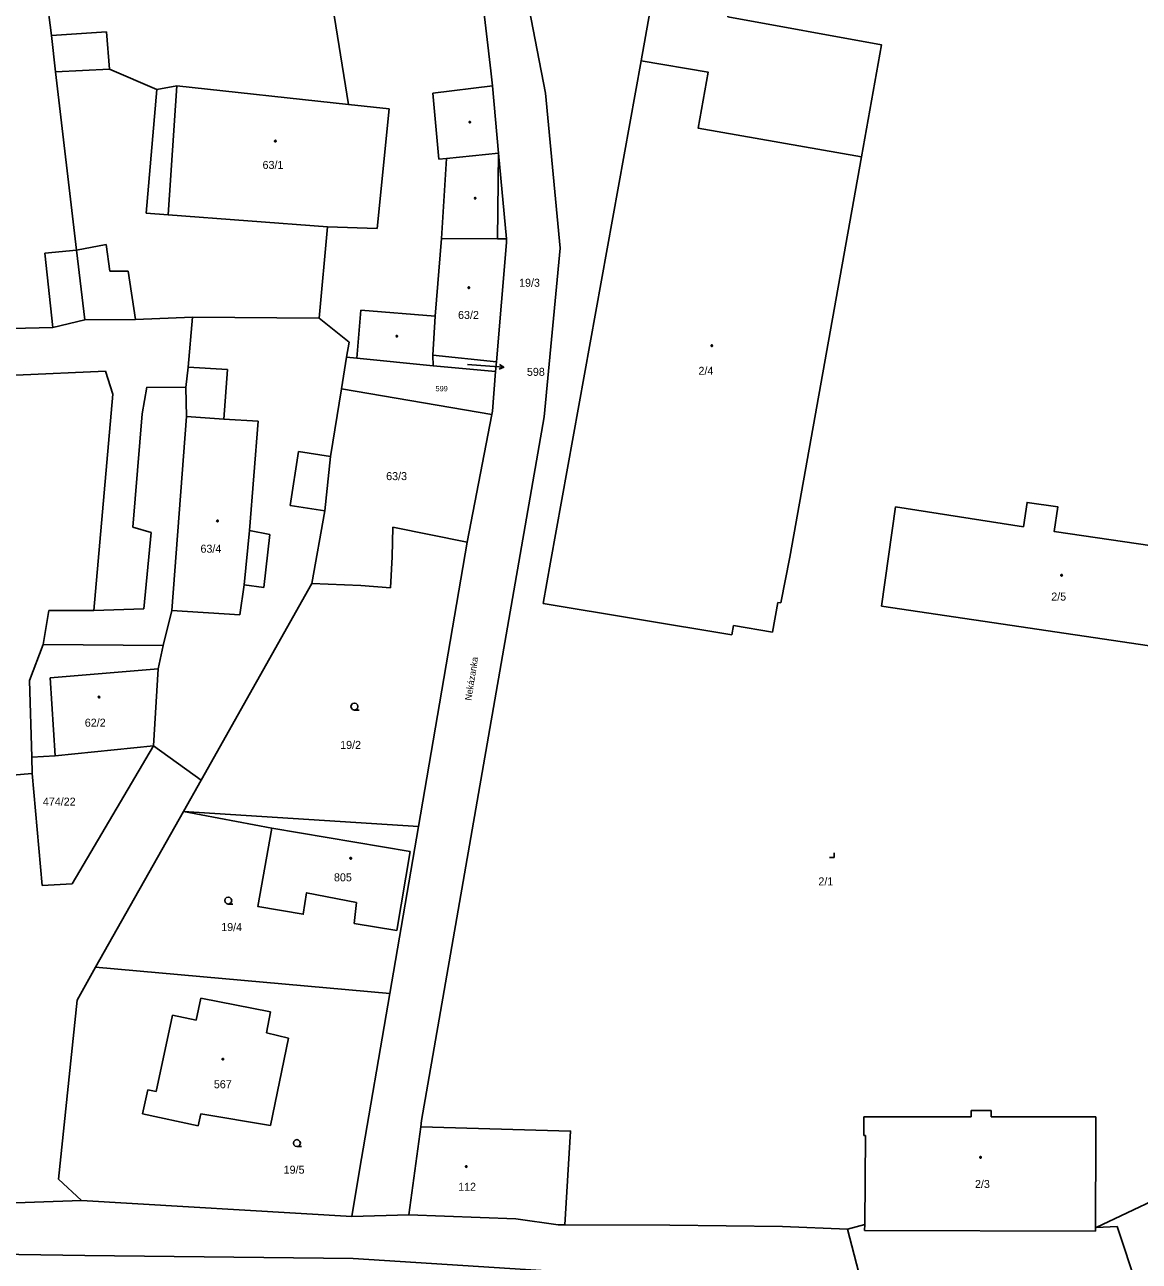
# Model space of a CAD drawing. Extents: x -757994 to -755874, y -1047691 to -1046119.
# Drawn here: x -757209.4 to -757091.1, y -1046980.7 to -1046849.4 of the extents above; entities that cross this region are included whole.
import ezdxf

# ---------------------------------------------------------------- set-up
doc = ezdxf.new("R2010")
doc.units = 0
doc.layers.add('katastrální mapa', color=7, linetype='Continuous')

msp = doc.modelspace()

# ---------------------------------------------------------------- linework, layer by layer
at = {"layer": 'katastrální mapa'}
for p, q in [((-757166.99, -1046790.73), (-757154.15, -1046856.61)), ((-757206.6, -1046850.49), (-757207.68, -1046842.04)), ((-757175.06, -1046857.82), (-757177.11, -1046845.16)), ((-757159.95, -1046854.25), (-757161.01, -1046845.29)), ((-757206.6, -1046850.49), (-757200.77, -1046850.13)), ((-757206.18, -1046854.36), (-757206.6, -1046850.49)), ((-757200.77, -1046850.13), (-757200.43, -1046854.08)), ((-757153.62, -1046906.44), (-757143.99, -1046853.18)), ((-757206.18, -1046854.36), (-757200.43, -1046854.08)), ((-757203.94, -1046873.31), (-757206.18, -1046854.36)), ((-757200.43, -1046854.08), (-757195.43, -1046856.24)), ((-757159.8, -1046855.86), (-757159.95, -1046854.25)), ((-757195.43, -1046856.24), (-757196.56, -1046869.36)), ((-757195.43, -1046856.24), (-757193.28, -1046855.84)), ((-757194.2, -1046869.53), (-757193.28, -1046855.84)), ((-757193.28, -1046855.84), (-757175.06, -1046857.82)), ((-757166.12, -1046856.61), (-757159.8, -1046855.86)), ((-757159.15, -1046862.98), (-757159.8, -1046855.86)), ((-757170.75, -1046858.29), (-757175.06, -1046857.82)), ((-757165.47, -1046863.65), (-757166.12, -1046856.61)), ((-757154.15, -1046856.61), (-757152.59, -1046873.09)), ((-757172.02, -1046871), (-757170.75, -1046858.29)), ((-757164.68, -1046863.57), (-757159.15, -1046862.98)), ((-757159.15, -1046862.98), (-757159.25, -1046872.09)), ((-757158.31, -1046872.1), (-757159.15, -1046862.98)), ((-757164.68, -1046863.57), (-757165.47, -1046863.65)), ((-757165.18, -1046872.05), (-757164.68, -1046863.57)), ((-757128.21, -1046905.88), (-757120.6, -1046863.38)), ((-757196.56, -1046869.36), (-757194.2, -1046869.53)), ((-757194.2, -1046869.53), (-757177.3, -1046870.83)), ((-757178.19, -1046880.51), (-757177.3, -1046870.83)), ((-757177.3, -1046870.83), (-757172.02, -1046871)), ((-757165.86, -1046880.32), (-757165.18, -1046872.05)), ((-757165.18, -1046872.05), (-757159.25, -1046872.09)), ((-757159.25, -1046872.09), (-757158.31, -1046872.1)), ((-757158.28, -1046872.47), (-757158.31, -1046872.1)), ((-757203.94, -1046873.31), (-757207.29, -1046873.61)), ((-757207.29, -1046873.61), (-757206.44, -1046881.51)), ((-757200.78, -1046872.68), (-757203.94, -1046873.31)), ((-757203.07, -1046880.69), (-757203.94, -1046873.31)), ((-757200.42, -1046875.51), (-757200.78, -1046872.68)), ((-757158.28, -1046872.47), (-757159.36, -1046885.16)), ((-757152.59, -1046873.09), (-757154.3, -1046890.98)), ((-757198.46, -1046875.54), (-757200.42, -1046875.51)), ((-757197.67, -1046880.67), (-757198.46, -1046875.54)), ((-757174.2, -1046884.77), (-757173.76, -1046879.67)), ((-757173.76, -1046879.67), (-757165.86, -1046880.32)), ((-757206.44, -1046881.51), (-757210.79, -1046881.6)), ((-757206.44, -1046881.51), (-757203.07, -1046880.69)), ((-757197.67, -1046880.67), (-757203.07, -1046880.69)), ((-757191.64, -1046880.4), (-757197.67, -1046880.67)), ((-757191.64, -1046880.4), (-757192.1, -1046885.71)), ((-757178.19, -1046880.51), (-757191.64, -1046880.4)), ((-757175.01, -1046883.05), (-757178.19, -1046880.51)), ((-757166.1, -1046884.43), (-757165.86, -1046880.32)), ((-757175.01, -1046883.05), (-757175.27, -1046884.67)), ((-757175.27, -1046884.67), (-757175.81, -1046888.02)), ((-757175.27, -1046884.67), (-757174.2, -1046884.77)), ((-757174.2, -1046884.77), (-757166.08, -1046885.56)), ((-757166.08, -1046885.56), (-757166.1, -1046884.43)), ((-757166.1, -1046884.43), (-757159.36, -1046885.16)), ((-757162.45, -1046885.42), (-757160.07, -1046885.61)), ((-757159.36, -1046885.16), (-757159.45, -1046886.19)), ((-757200.85, -1046886.14), (-757210.37, -1046886.58)), ((-757200.1, -1046888.59), (-757200.85, -1046886.14)), ((-757192.1, -1046885.71), (-757192.34, -1046887.86)), ((-757187.9, -1046885.98), (-757192.1, -1046885.71)), ((-757188.31, -1046891.24), (-757187.9, -1046885.98)), ((-757166.08, -1046885.56), (-757159.45, -1046886.19)), ((-757158.58, -1046885.73), (-757160.07, -1046885.61)), ((-757159.8, -1046890.39), (-757159.45, -1046886.19)), ((-757196.46, -1046887.83), (-757196.98, -1046890.68)), ((-757192.34, -1046887.86), (-757196.46, -1046887.83)), ((-757192.34, -1046887.86), (-757192.27, -1046890.94)), ((-757175.81, -1046888.02), (-757176.97, -1046895.2)), ((-757175.81, -1046888.02), (-757159.86, -1046890.74)), ((-757202.1, -1046911.55), (-757200.1, -1046888.59)), ((-757196.98, -1046890.68), (-757197.97, -1046902.72)), ((-757159.86, -1046890.74), (-757159.8, -1046890.39)), ((-757192.27, -1046890.94), (-757193.82, -1046911.57)), ((-757188.31, -1046891.24), (-757192.27, -1046890.94)), ((-757184.64, -1046891.45), (-757188.31, -1046891.24)), ((-757185.57, -1046903.05), (-757184.64, -1046891.45)), ((-757167.31, -1046965.72), (-757154.3, -1046890.98)), ((-757162.46, -1046904.29), (-757159.86, -1046890.74)), ((-757181.26, -1046900.41), (-757180.38, -1046894.69)), ((-757180.38, -1046894.69), (-757176.97, -1046895.2)), ((-757176.97, -1046895.2), (-757177.57, -1046900.98)), ((-757177.57, -1046900.98), (-757181.26, -1046900.41)), ((-757177.57, -1046900.98), (-757178.95, -1046908.7)), ((-757197.97, -1046902.72), (-757196.03, -1046903.27)), ((-757196.03, -1046903.27), (-757196.8, -1046911.36)), ((-757185.57, -1046903.05), (-757186.13, -1046908.83)), ((-757183.43, -1046903.49), (-757185.57, -1046903.05)), ((-757184.06, -1046909.1), (-757183.43, -1046903.49)), ((-757170.37, -1046902.69), (-757170.43, -1046905.86)), ((-757162.46, -1046904.29), (-757170.37, -1046902.69)), ((-757167.64, -1046934.49), (-757162.46, -1046904.29)), ((-757170.43, -1046905.86), (-757170.61, -1046909.13)), ((-757153.62, -1046906.44), (-757154.42, -1046910.82)), ((-757128.21, -1046905.88), (-757129.17, -1046910.75)), ((-757178.95, -1046908.7), (-757190.72, -1046929.57)), ((-757186.59, -1046912.01), (-757186.13, -1046908.83)), ((-757186.13, -1046908.83), (-757184.06, -1046909.1)), ((-757173.76, -1046908.91), (-757178.95, -1046908.7)), ((-757170.61, -1046909.13), (-757173.76, -1046908.91)), ((-757206.87, -1046911.57), (-757207.47, -1046915.17)), ((-757202.1, -1046911.55), (-757206.87, -1046911.57)), ((-757196.8, -1046911.36), (-757202.1, -1046911.55)), ((-757193.82, -1046911.57), (-757194.74, -1046915.28)), ((-757193.82, -1046911.57), (-757186.59, -1046912.01)), ((-757154.42, -1046910.82), (-757134.37, -1046914.13)), ((-757130.05, -1046913.87), (-757129.51, -1046910.7)), ((-757129.17, -1046910.75), (-757129.51, -1046910.7)), ((-757118.49, -1046911.08), (-757080.24, -1046916.75)), ((-757134.37, -1046914.13), (-757134.21, -1046913.16)), ((-757134.21, -1046913.16), (-757130.05, -1046913.87)), ((-757207.47, -1046915.17), (-757208.92, -1046918.97)), ((-757194.74, -1046915.28), (-757207.47, -1046915.17)), ((-757194.74, -1046915.28), (-757195.27, -1046917.74)), ((-757206.74, -1046918.69), (-757195.27, -1046917.74)), ((-757195.27, -1046917.74), (-757195.77, -1046925.93)), ((-757208.92, -1046918.97), (-757208.68, -1046927.13)), ((-757206.2, -1046926.99), (-757206.74, -1046918.69)), ((-757195.77, -1046925.93), (-757206.2, -1046926.99)), ((-757204.4, -1046940.59), (-757195.77, -1046925.93)), ((-757190.72, -1046929.57), (-757195.77, -1046925.93)), ((-757206.2, -1046926.99), (-757208.68, -1046927.13)), ((-757208.68, -1046927.13), (-757208.63, -1046928.85)), ((-757208.63, -1046928.85), (-757215.51, -1046929.42)), ((-757208.63, -1046928.85), (-757207.58, -1046940.75)), ((-757192.59, -1046932.88), (-757190.72, -1046929.57)), ((-757201.92, -1046949.43), (-757192.59, -1046932.88)), ((-757167.64, -1046934.49), (-757192.59, -1046932.88)), ((-757183.22, -1046934.68), (-757192.59, -1046932.88)), ((-757168.52, -1046937.14), (-757183.22, -1046934.68)), ((-757170.68, -1046952.23), (-757167.64, -1046934.49)), ((-757168.52, -1046937.14), (-757169.93, -1046945.54)), ((-757207.58, -1046940.75), (-757204.4, -1046940.59)), ((-757169.93, -1046945.54), (-757174.45, -1046944.79)), ((-757203.88, -1046952.91), (-757201.92, -1046949.43)), ((-757170.68, -1046952.23), (-757201.92, -1046949.43)), ((-757173.89, -1046970.96), (-757170.68, -1046952.23)), ((-757205.86, -1046971.94), (-757203.88, -1046952.91)), ((-757191.23, -1046955.05), (-757190.74, -1046952.72)), ((-757190.74, -1046952.72), (-757183.36, -1046954.16)), ((-757195.48, -1046962.64), (-757193.76, -1046954.51)), ((-757193.76, -1046954.51), (-757191.23, -1046955.05)), ((-757183.36, -1046954.16), (-757183.77, -1046956.38)), ((-757183.77, -1046956.38), (-757181.43, -1046956.96)), ((-757181.43, -1046956.96), (-757183.35, -1046966.22)), ((-757196.92, -1046965.01), (-757196.38, -1046962.45)), ((-757196.38, -1046962.45), (-757195.48, -1046962.64)), ((-757191.02, -1046966.26), (-757196.92, -1046965.01)), ((-757190.75, -1046964.99), (-757191.02, -1046966.26)), ((-757183.35, -1046966.22), (-757190.75, -1046964.99)), ((-757120.37, -1046967.29), (-757120.36, -1046965.3)), ((-757120.36, -1046965.3), (-757108.99, -1046965.31)), ((-757108.99, -1046965.31), (-757108.99, -1046964.64)), ((-757108.99, -1046964.64), (-757106.86, -1046964.65)), ((-757106.86, -1046964.65), (-757106.86, -1046965.32)), ((-757106.86, -1046965.32), (-757095.74, -1046965.33)), ((-757095.74, -1046965.33), (-757095.75, -1046967.32)), ((-757167.4, -1046966.36), (-757168.67, -1046975.71)), ((-757167.31, -1046965.72), (-757167.4, -1046966.36)), ((-757120.2, -1046967.29), (-757120.37, -1046967.29)), ((-757120.27, -1046976.75), (-757120.2, -1046967.29)), ((-757095.75, -1046967.32), (-757095.76, -1046977.06)), ((-757203.42, -1046974.2), (-757205.86, -1046971.94)), ((-757174.73, -1046975.89), (-757173.89, -1046970.96)), ((-757221.74, -1046974.83), (-757203.42, -1046974.2)), ((-757174.73, -1046975.89), (-757203.42, -1046974.2)), ((-757095.69, -1046977.06), (-757089.11, -1046973.95)), ((-757168.67, -1046975.71), (-757174.73, -1046975.89)), ((-757168.67, -1046975.71), (-757157.29, -1046976.14)), ((-757157.29, -1046976.14), (-757152.82, -1046976.77)), ((-757152.82, -1046976.77), (-757152.09, -1046976.77)), ((-757152.09, -1046976.77), (-757140.95, -1046976.81)), ((-757140.95, -1046976.81), (-757129.01, -1046976.95)), ((-757129.01, -1046976.95), (-757122.09, -1046977.24)), ((-757120.27, -1046976.75), (-757122.09, -1046977.24)), ((-757122.09, -1046977.24), (-757118.46, -1046991.34)), ((-757120.28, -1046977.4), (-757120.27, -1046976.75)), ((-757095.76, -1046977.06), (-757095.76, -1046977.45)), ((-757095.76, -1046977.06), (-757095.69, -1046977.06)), ((-757095.69, -1046977.06), (-757093.47, -1046976.95)), ((-757093.47, -1046976.95), (-757091.35, -1046983.35)), ((-757095.76, -1046977.45), (-757120.28, -1046977.4)), ((-757203.07, -1046980.03), (-757268.25, -1046979.12)), ((-757203.07, -1046980.03), (-757174.57, -1046980.37)), ((-757174.57, -1046980.37), (-757133.55, -1046982.97))]:
    msp.add_line(p, q, dxfattribs=at)
for points in [[(-757120.6, -1046863.38), (-757118.5, -1046851.48), (-757134.8, -1046848.52), (-757133.7, -1046842.55), (-757141.88, -1046841.24), (-757143.99, -1046853.18)], [(-757143.99, -1046853.18), (-757136.88, -1046854.4), (-757137.95, -1046860.36), (-757120.6, -1046863.38)], [(-757159.05, -1046885.44), (-757158.58, -1046885.73), (-757159.09, -1046885.94)], [(-757118.49, -1046911.08), (-757117, -1046900.56), (-757103.42, -1046902.66), (-757103.03, -1046900.08), (-757099.78, -1046900.53), (-757100.18, -1046903.15), (-757077.9, -1046906.42)], [(-757174.44, -1046922.12), (-757174.63, -1046922.07), (-757174.76, -1046921.94), (-757174.82, -1046921.75), (-757174.76, -1046921.57), (-757174.63, -1046921.43), (-757174.45, -1046921.38), (-757174.26, -1046921.43), (-757174.12, -1046921.57), (-757174.08, -1046921.76), (-757174.12, -1046921.95), (-757174.26, -1046922.08), (-757174.45, -1046922.13), (-757173.95, -1046922.13)], [(-757183.22, -1046934.68), (-757184.71, -1046942.97), (-757179.88, -1046943.81), (-757179.51, -1046941.52), (-757174.22, -1046942.56), (-757174.45, -1046944.79)], [(-757124.02, -1046937.77), (-757123.52, -1046937.77), (-757123.52, -1046937.27)], [(-757187.83, -1046942.72), (-757188.02, -1046942.67), (-757188.16, -1046942.53), (-757188.21, -1046942.35), (-757188.16, -1046942.17), (-757188.02, -1046942.03), (-757187.84, -1046941.98), (-757187.65, -1046942.03), (-757187.51, -1046942.17), (-757187.47, -1046942.36), (-757187.51, -1046942.54), (-757187.65, -1046942.68), (-757187.84, -1046942.73), (-757187.34, -1046942.73)], [(-757167.4, -1046966.36), (-757151.5, -1046966.82), (-757152.09, -1046976.77)], [(-757180.54, -1046968.47), (-757180.73, -1046968.42), (-757180.86, -1046968.28), (-757180.92, -1046968.1), (-757180.86, -1046967.92), (-757180.73, -1046967.78), (-757180.55, -1046967.73), (-757180.36, -1046967.78), (-757180.23, -1046967.92), (-757180.18, -1046968.11), (-757180.23, -1046968.29), (-757180.36, -1046968.43), (-757180.55, -1046968.48), (-757180.05, -1046968.48)]]:
    msp.add_lwpolyline(points, dxfattribs=at)
for points in [[(-757162.15, -1046859.62), (-757162.1, -1046859.7), (-757162.15, -1046859.77), (-757162.23, -1046859.77), (-757162.28, -1046859.7), (-757162.23, -1046859.62)], [(-757182.83, -1046861.62), (-757182.78, -1046861.64), (-757182.75, -1046861.68), (-757182.74, -1046861.71), (-757182.75, -1046861.75), (-757182.79, -1046861.79), (-757182.83, -1046861.79), (-757182.88, -1046861.78), (-757182.91, -1046861.75), (-757182.92, -1046861.71), (-757182.91, -1046861.67), (-757182.86, -1046861.63)], [(-757161.58, -1046867.71), (-757161.53, -1046867.78), (-757161.58, -1046867.86), (-757161.67, -1046867.86), (-757161.71, -1046867.78), (-757161.67, -1046867.71)], [(-757162.29, -1046877.2), (-757162.24, -1046877.21), (-757162.22, -1046877.25), (-757162.21, -1046877.28), (-757162.22, -1046877.33), (-757162.26, -1046877.36), (-757162.29, -1046877.37), (-757162.34, -1046877.35), (-757162.36, -1046877.32), (-757162.38, -1046877.28), (-757162.36, -1046877.24), (-757162.33, -1046877.2)], [(-757169.89, -1046882.35), (-757169.84, -1046882.42), (-757169.89, -1046882.5), (-757169.98, -1046882.5), (-757170.02, -1046882.42), (-757169.98, -1046882.35)], [(-757136.49, -1046883.36), (-757136.44, -1046883.37), (-757136.42, -1046883.41), (-757136.41, -1046883.44), (-757136.42, -1046883.48), (-757136.46, -1046883.52), (-757136.49, -1046883.52), (-757136.53, -1046883.51), (-757136.57, -1046883.48), (-757136.58, -1046883.44), (-757136.57, -1046883.4), (-757136.52, -1046883.36)], [(-757188.98, -1046901.97), (-757188.93, -1046901.98), (-757188.91, -1046902.02), (-757188.9, -1046902.05), (-757188.91, -1046902.1), (-757188.95, -1046902.13), (-757188.98, -1046902.14), (-757189.02, -1046902.12), (-757189.05, -1046902.09), (-757189.07, -1046902.05), (-757189.05, -1046902.01), (-757189.01, -1046901.97)], [(-757099.38, -1046907.73), (-757099.33, -1046907.74), (-757099.3, -1046907.79), (-757099.29, -1046907.82), (-757099.3, -1046907.87), (-757099.35, -1046907.9), (-757099.38, -1046907.91), (-757099.43, -1046907.89), (-757099.46, -1046907.86), (-757099.47, -1046907.82), (-757099.46, -1046907.77), (-757099.42, -1046907.74)], [(-757201.55, -1046920.66), (-757201.5, -1046920.67), (-757201.48, -1046920.71), (-757201.47, -1046920.74), (-757201.48, -1046920.78), (-757201.52, -1046920.82), (-757201.55, -1046920.83), (-757201.6, -1046920.81), (-757201.62, -1046920.78), (-757201.64, -1046920.74), (-757201.62, -1046920.7), (-757201.59, -1046920.66)], [(-757174.84, -1046937.77), (-757174.79, -1046937.78), (-757174.76, -1046937.83), (-757174.75, -1046937.86), (-757174.76, -1046937.91), (-757174.8, -1046937.94), (-757174.84, -1046937.95), (-757174.89, -1046937.93), (-757174.92, -1046937.9), (-757174.93, -1046937.86), (-757174.92, -1046937.82), (-757174.88, -1046937.78)], [(-757188.4, -1046959.11), (-757188.35, -1046959.12), (-757188.33, -1046959.16), (-757188.32, -1046959.19), (-757188.33, -1046959.23), (-757188.36, -1046959.27), (-757188.4, -1046959.27), (-757188.45, -1046959.26), (-757188.48, -1046959.23), (-757188.49, -1046959.19), (-757188.48, -1046959.15), (-757188.44, -1046959.11)], [(-757162.56, -1046970.5), (-757162.51, -1046970.51), (-757162.49, -1046970.56), (-757162.48, -1046970.59), (-757162.49, -1046970.64), (-757162.53, -1046970.67), (-757162.56, -1046970.68), (-757162.6, -1046970.66), (-757162.64, -1046970.63), (-757162.65, -1046970.59), (-757162.64, -1046970.54), (-757162.6, -1046970.51)], [(-757107.98, -1046969.53), (-757107.93, -1046969.54), (-757107.91, -1046969.59), (-757107.9, -1046969.62), (-757107.91, -1046969.67), (-757107.95, -1046969.7), (-757107.98, -1046969.71), (-757108.02, -1046969.69), (-757108.05, -1046969.66), (-757108.07, -1046969.62), (-757108.05, -1046969.58), (-757108.01, -1046969.54)]]:
    msp.add_lwpolyline(points, close=True, dxfattribs=at)

# ---------------------------------------------------------------- texts
for s, height, p in [('63/1', 0.85, (-757184.19, -1046864.67)), ('19/3', 0.85, (-757156.96, -1046877.18)), ('63/2', 0.85, (-757163.44, -1046880.6)), ('598', 0.05, (-757162.51, -1046885.42)), ('598', 0.85, (-757156.13, -1046886.64)), ('2/4', 0.85, (-757137.92, -1046886.53)), ('599', 0.57, (-757165.84, -1046888.28)), ('63/3', 0.85, (-757171.07, -1046897.71)), ('63/4', 0.85, (-757190.78, -1046905.42)), ('2/5', 0.85, (-757100.47, -1046910.5)), ('62/2', 0.85, (-757203.06, -1046923.89)), ('19/2', 0.85, (-757175.95, -1046926.25)), ('474/22', 0.85, (-757207.51, -1046932.27)), ('805', 0.85, (-757176.61, -1046940.31)), ('2/1', 0.85, (-757125.19, -1046940.74)), ('19/4', 0.85, (-757188.58, -1046945.59)), ('567', 0.85, (-757189.36, -1046962.28)), ('19/5', 0.85, (-757181.95, -1046971.35)), ('2/3', 0.85, (-757108.57, -1046972.87)), ('112', 0.85, (-757163.43, -1046973.17))]:
    msp.add_text(s, height=height, dxfattribs=at).set_placement(p)
msp.add_text('Nekázanka', height=0.7, rotation=81.0735, dxfattribs=at).set_placement((-757162.03, -1046921.16))

doc.saveas('drawing.dxf')
